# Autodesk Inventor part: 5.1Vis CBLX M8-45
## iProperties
Created: 2011-01
Part Number: 5.1Vis CBLX M8-45
Document SubType Name: Modeling
Designer: eric
Density: 1 g/cm^3
Mass: 3.13907 g
Surface Area: 17.5326 cm^2
Volume: 3.13907 cm^3
Author: eric
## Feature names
1. Base1
